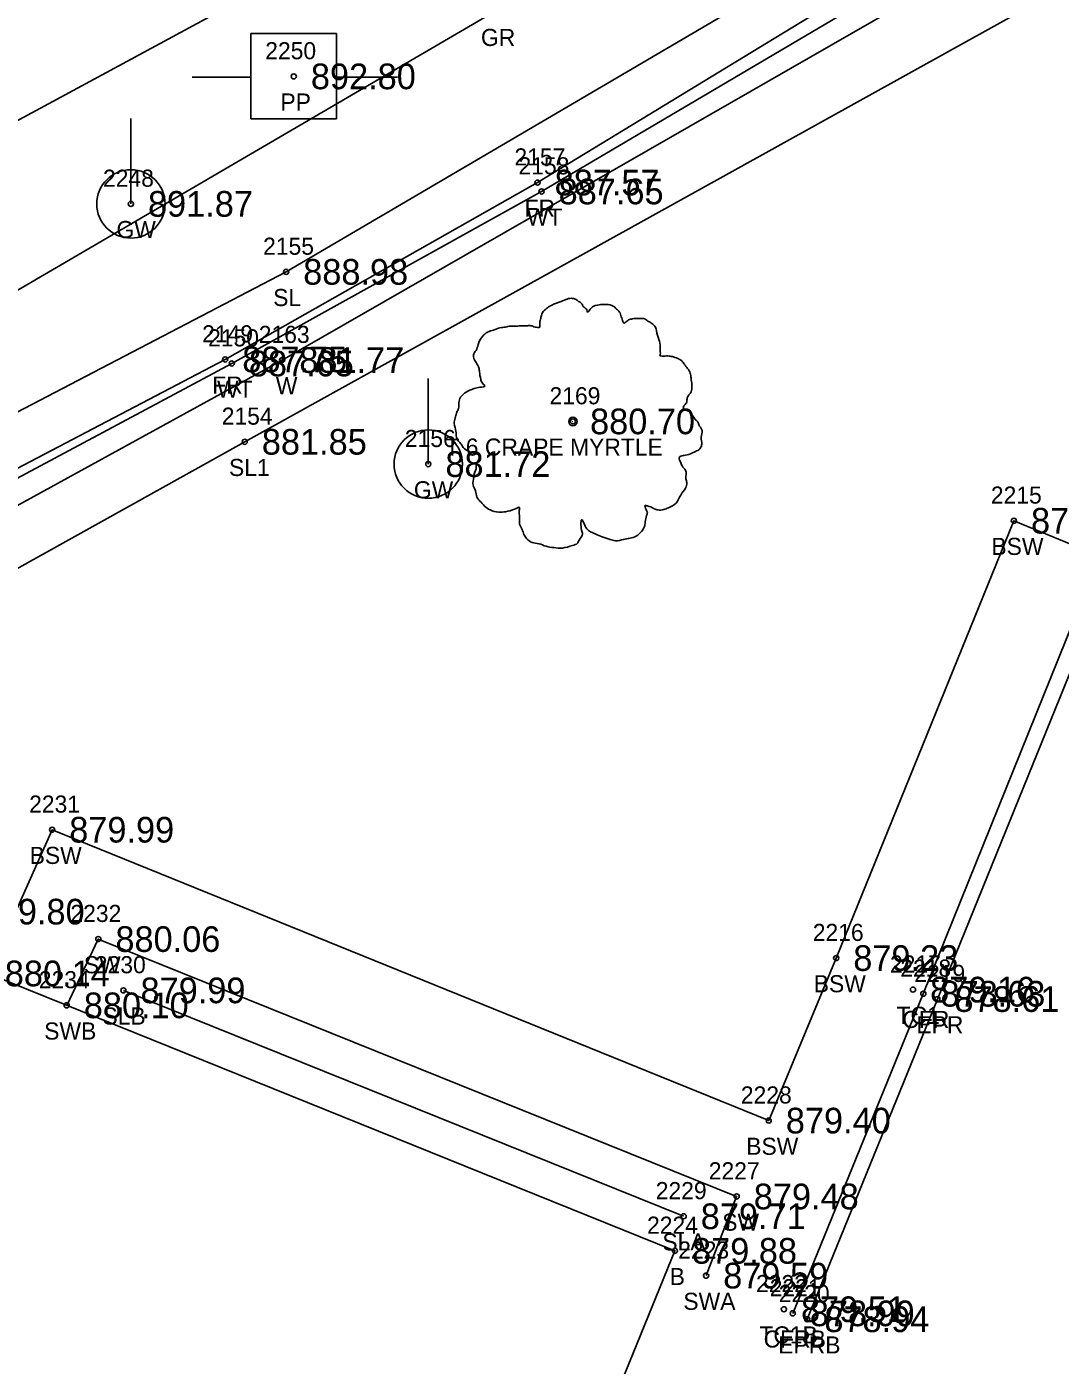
# Model space of a CAD drawing. Extents: x 1622501 to 1626664, y 1117816 to 1121579.
# Drawn here: x 1623395.8 to 1623456.2, y 1118647.2 to 1118725.4 of the extents above; entities that cross this region are included whole.
import ezdxf

# ---------------------------------------------------------------- set-up
doc = ezdxf.new("R2010")
doc.units = 0
for name, color, linetype in [('RD_EX_Bldg', 7, 'Continuous'), ('RD_EX_Bldg_txCode', 7, 'Continuous'), ('RD_EX_BldgApp', 7, 'Continuous'), ('RD_EX_Conc', 7, 'Continuous'), ('RD_EX_Conc_txCode', 7, 'Continuous'), ('RD_EX_Fence_Other', 7, 'Continuous'), ('RD_EX_Fence_Other_txCode', 7, 'Continuous'), ('RD_EX_GuardRail', 7, 'Continuous'), ('RD_EX_GuardRail_txCode', 7, 'Continuous'), ('RD_EX_Misc', 7, 'Continuous'), ('RD_EX_Misc_txCode', 7, 'Continuous'), ('RD_EX_Road', 7, 'Continuous'), ('RD_EX_Road_txCode', 7, 'Continuous'), ('RD_EX_TX_Bldg_ELEV', 7, 'Continuous'), ('RD_EX_TX_Conc_ELEV', 7, 'Continuous'), ('RD_EX_TX_Fence_Other_ELEV', 7, 'Continuous'), ('RD_EX_TX_Misc_ELEV', 7, 'Continuous'), ('RD_EX_TX_Road_ELEV', 7, 'Continuous'), ('RD_EX_TX_UT_ELEV', 7, 'Continuous'), ('RD_EX_TX_VEG_ELEV', 7, 'Continuous'), ('RD_EX_UT', 7, 'Continuous'), ('RD_EX_UT_txCode', 7, 'Continuous'), ('RD_EX_VEG', 7, 'Continuous'), ('RD_EX_VEG_txCode', 7, 'Continuous'), ('RD_HC_Survey_ELEV', 7, 'Continuous'), ('RD_SMD_Locator', 7, 'Continuous')]:
    doc.layers.add(name, color=color, linetype=linetype)

msp = doc.modelspace()

# ---------------------------------------------------------------- linework, layer by layer
at = {"layer": 'RD_EX_Bldg'}
msp.add_lwpolyline([(1623351.424, 1118597.995), (1623382.58, 1118674.507), (1623433.654, 1118653.895), (1623402.498, 1118577.383), (1623351.424, 1118597.995)], dxfattribs=at)
at = {"layer": 'RD_EX_BldgApp'}
msp.add_lwpolyline([(1623362.832, 1118662.827), (1623370.193, 1118681.931), (1623373.866, 1118685.757), (1623410.694, 1118705.967), (1623459.429, 1118733.933), (1623484.083, 1118750.076), (1623515.96, 1118771.434)], dxfattribs=at)
at = {"layer": 'RD_EX_Conc'}
for points in [[(1623287.102, 1118659.692), (1623329.453, 1118683.877), (1623372.881, 1118707.9), (1623416.572, 1118731.516), (1623459.835, 1118756.855), (1623502.097, 1118784.616), (1623542.536, 1118813.857), (1623581.966, 1118844.894), (1623613.887, 1118871.887), (1623619.415, 1118875.421), (1623623.688, 1118876.741), (1623623.459, 1118877.275), (1623631.268, 1118878.694), (1623634.056, 1118878.854), (1623639.628, 1118878.454), (1623640.557, 1118883.374)], [(1623531.882, 1118716.271), (1623516.156, 1118720.453), (1623505.692, 1118721.141), (1623486.378, 1118717.233), (1623473.832, 1118710.301), (1623464.844, 1118702.769), (1623477.624, 1118690.682), (1623478.738, 1118687.446), (1623474.882, 1118687.167), (1623458.276, 1118693.978), (1623448.175, 1118668.923), (1623440.54, 1118650.24)], [(1623458.019, 1118694.702), (1623453.469, 1118696.574), (1623443.082, 1118671.009), (1623439.137, 1118661.507), (1623397.246, 1118678.511), (1623393.478, 1118670.109)], [(1623435.477, 1118652.445), (1623437.262, 1118657.073), (1623399.945, 1118672.119), (1623398.097, 1118668.245)]]:
    msp.add_lwpolyline(points, dxfattribs=at)
at = {"layer": 'RD_EX_Fence_Other'}
msp.add_lwpolyline([(1623360.82, 1118663.932), (1623367.011, 1118680.639), (1623370.331, 1118685.573), (1623375.249, 1118689.174), (1623407.361, 1118706.001), (1623425.619, 1118716.341), (1623480.358, 1118749.66), (1623515.549, 1118772.603)], dxfattribs=at)
at = {"layer": 'RD_EX_GuardRail'}
msp.add_lwpolyline([(1623328.796, 1118667.195), (1623333.583, 1118673.211), (1623349.309, 1118682.841), (1623377.56, 1118699.748), (1623423.094, 1118726.327), (1623463.83, 1118751.666), (1623511.133, 1118780.414)], dxfattribs=at)
at = {"layer": 'RD_EX_Misc'}
msp.add_lwpolyline([(1623362.047, 1118663.092), (1623363.077, 1118666.011), (1623364.471, 1118669.561), (1623365.33, 1118671.673), (1623366.043, 1118673.822), (1623367.273, 1118677.387), (1623367.858, 1118679.553), (1623368.979, 1118682.037), (1623371.277, 1118685.581), (1623375.298, 1118688.415), (1623407.747, 1118705.764), (1623425.855, 1118715.821), (1623458.998, 1118735.378), (1623483.907, 1118751.097), (1623484.139, 1118751.024), (1623515.704, 1118772.555)], dxfattribs=at)
at = {"layer": 'RD_EX_Road'}
msp.add_lwpolyline([(1623529.611, 1118716.171), (1623516.152, 1118719.483), (1623505.742, 1118720.286), (1623486.757, 1118716.386), (1623474.282, 1118709.658), (1623466.206, 1118702.886), (1623478.169, 1118691.689), (1623479.562, 1118687.18), (1623474.442, 1118686.423), (1623458.812, 1118692.747), (1623448.994, 1118668.612), (1623441.391, 1118649.895)], dxfattribs=at)
at = {"layer": 'RD_EX_UT'}
for p, q in [((1623413.863, 1118725.058), (1623408.863, 1118725.058)), ((1623408.863, 1118725.058), (1623408.863, 1118720.058)), ((1623413.863, 1118720.058), (1623413.863, 1118725.058)), ((1623405.432, 1118722.495), (1623408.901, 1118722.495)), ((1623413.791, 1118722.495), (1623417.432, 1118722.495)), ((1623401.849, 1118715.096), (1623401.849, 1118720.096)), ((1623408.863, 1118720.058), (1623413.863, 1118720.058)), ((1623419.236, 1118699.883), (1623419.236, 1118704.883))]:
    msp.add_line(p, q, dxfattribs=at)
for centre in [(1623401.849, 1118715.096), (1623419.236, 1118699.883)]:
    msp.add_circle(centre, 1.999, dxfattribs=at)
at = {"layer": 'RD_EX_VEG'}
msp.add_line((1623434.163, 1118655.915), (1623401.413, 1118669.12), dxfattribs=at)
for points in [[(1623371.315, 1118690.471), (1623410.924, 1118711.122), (1623478.591, 1118750.831), (1623514.185, 1118775.518)], [(1623357.099, 1118658.576), (1623354.417, 1118653.307), (1623360.309, 1118652.881), (1623372.824, 1118681.33), (1623408.505, 1118701.188), (1623470.644, 1118735.679), (1623505.961, 1118762.905)]]:
    msp.add_lwpolyline(points, dxfattribs=at)
for centre, radius in [((1623427.692, 1118702.38), 0.25), ((1623427.679, 1118702.361), 0.0001)]:
    msp.add_circle(centre, radius, dxfattribs=at)
for points in [[(1623427.824, 1118709.547), (1623427.524, 1118709.572), (1623427.199, 1118709.472), (1623426.949, 1118709.372), (1623426.724, 1118709.297), (1623426.499, 1118709.197), (1623426.199, 1118709.022), (1623425.975, 1118708.822), (1623425.85, 1118708.573), (1623425.8, 1118708.348), (1623425.75, 1118708.073), (1623425.75, 1118707.898), (1623425.625, 1118707.873), (1623425.475, 1118707.898), (1623425.225, 1118707.973), (1623424.975, 1118707.973), (1623424.725, 1118707.973), (1623424.375, 1118707.948), (1623424.025, 1118707.948), (1623423.751, 1118707.898), (1623423.426, 1118707.848), (1623423.051, 1118707.723), (1623422.701, 1118707.598), (1623422.401, 1118707.348), (1623422.151, 1118706.873), (1623422.026, 1118706.523), (1623421.876, 1118706.274), (1623422.026, 1118705.824), (1623422.201, 1118705.474), (1623422.226, 1118705.274), (1623422.301, 1118704.849), (1623422.401, 1118704.624), (1623422.526, 1118704.424), (1623422.451, 1118704.399), (1623422.076, 1118704.349), (1623421.776, 1118704.249), (1623421.352, 1118704.025), (1623421.127, 1118703.8), (1623421.027, 1118703.475), (1623421.002, 1118703.125), (1623420.902, 1118702.925), (1623420.827, 1118702.65), (1623420.802, 1118702.575), (1623420.752, 1118702.25), (1623420.852, 1118701.8), (1623420.877, 1118701.451), (1623421.002, 1118701.226), (1623421.152, 1118701.051), (1623421.327, 1118700.801), (1623421.726, 1118700.576), (1623422.051, 1118700.476), (1623422.251, 1118700.451), (1623422.076, 1118699.951), (1623422.026, 1118699.601), (1623421.901, 1118699.202), (1623421.901, 1118699.127), (1623421.851, 1118698.652), (1623422.001, 1118698.327), (1623422.076, 1118697.952), (1623422.251, 1118697.727), (1623422.526, 1118697.427), (1623422.851, 1118697.203), (1623423.351, 1118697.078), (1623423.751, 1118697.103), (1623424.325, 1118697.277), (1623424.575, 1118697.352), (1623424.55, 1118697.178), (1623424.575, 1118696.803), (1623424.575, 1118696.378), (1623424.725, 1118696.053), (1623424.825, 1118695.778), (1623424.975, 1118695.528), (1623425.3, 1118695.303), (1623425.7, 1118695.228), (1623426.124, 1118695.078), (1623426.574, 1118695.003), (1623427.074, 1118694.978), (1623427.674, 1118695.128), (1623427.949, 1118695.253), (1623428.049, 1118695.428), (1623428.249, 1118695.803), (1623428.199, 1118696.028), (1623428.224, 1118696.628), (1623428.323, 1118696.453), (1623428.498, 1118696.103), (1623428.998, 1118695.803), (1623429.398, 1118695.628), (1623429.873, 1118695.478), (1623430.173, 1118695.403), (1623430.647, 1118695.478), (1623431.022, 1118695.553), (1623431.397, 1118695.678), (1623431.697, 1118695.953), (1623431.872, 1118696.228), (1623431.922, 1118696.503), (1623431.997, 1118696.878), (1623432.047, 1118697.053)], [(1623432.047, 1118697.053), (1623431.972, 1118697.228), (1623431.922, 1118697.477), (1623431.997, 1118697.452), (1623432.172, 1118697.402), (1623432.447, 1118697.277), (1623432.672, 1118697.203), (1623432.996, 1118697.228), (1623433.271, 1118697.327), (1623433.721, 1118697.602), (1623433.996, 1118698.077), (1623434.271, 1118698.477), (1623434.346, 1118698.802), (1623434.296, 1118699.027), (1623434.271, 1118699.526), (1623434.071, 1118699.776), (1623434.021, 1118699.901), (1623433.921, 1118700.301), (1623433.996, 1118700.351), (1623434.271, 1118700.401), (1623434.646, 1118700.526), (1623434.921, 1118700.651), (1623435.146, 1118700.826), (1623435.22, 1118701.051), (1623435.196, 1118701.451), (1623435.245, 1118701.85), (1623435.171, 1118702), (1623435.071, 1118702.15), (1623434.996, 1118702.35), (1623434.846, 1118702.5), (1623434.746, 1118702.65), (1623434.646, 1118702.75), (1623434.521, 1118702.9), (1623434.346, 1118703.025), (1623434.196, 1118703.075), (1623434.146, 1118703.225), (1623434.296, 1118703.425), (1623434.346, 1118703.525), (1623434.371, 1118703.75), (1623434.596, 1118704.099), (1623434.646, 1118704.499), (1623434.596, 1118704.924), (1623434.546, 1118705.199), (1623434.396, 1118705.474), (1623434.196, 1118705.724), (1623434.071, 1118705.899), (1623433.896, 1118706.024), (1623433.571, 1118706.149), (1623433.321, 1118706.199), (1623432.971, 1118706.199), (1623432.772, 1118706.249), (1623432.797, 1118706.299), (1623432.797, 1118706.448), (1623432.797, 1118706.723), (1623432.722, 1118707.173), (1623432.572, 1118707.673), (1623432.572, 1118707.698), (1623432.472, 1118707.948), (1623432.247, 1118708.148), (1623432.072, 1118708.248), (1623431.872, 1118708.373), (1623431.622, 1118708.398), (1623431.322, 1118708.398), (1623431.047, 1118708.348), (1623430.847, 1118708.248), (1623430.672, 1118708.123), (1623430.597, 1118708.273), (1623430.498, 1118708.573), (1623430.448, 1118708.722), (1623430.298, 1118708.897), (1623430.073, 1118709.097), (1623429.623, 1118709.222), (1623428.998, 1118709.147), (1623428.698, 1118708.947), (1623428.548, 1118708.772), (1623428.498, 1118708.897), (1623428.298, 1118709.097), (1623428.199, 1118709.272), (1623428.024, 1118709.397), (1623427.874, 1118709.497), (1623427.774, 1118709.547)]]:
    msp.add_spline(points, degree=3, dxfattribs=at)
at = {"layer": 'RD_SMD_Locator'}
for centre in [(1623411.372, 1118722.549), (1623425.619, 1118716.341), (1623425.855, 1118715.821), (1623401.849, 1118715.096), (1623410.924, 1118711.122), (1623407.361, 1118706.001), (1623410.694, 1118705.967), (1623407.747, 1118705.764), (1623427.692, 1118702.38), (1623408.505, 1118701.188), (1623419.236, 1118699.883), (1623453.469, 1118696.574), (1623397.246, 1118678.511), (1623399.945, 1118672.119), (1623443.082, 1118671.009), (1623401.413, 1118669.12), (1623447.571, 1118669.164), (1623448.175, 1118668.923), (1623448.994, 1118668.612), (1623398.097, 1118668.245), (1623439.137, 1118661.507), (1623437.262, 1118657.073), (1623434.163, 1118655.915), (1623433.654, 1118653.895), (1623435.477, 1118652.445), (1623440.023, 1118650.48), (1623440.54, 1118650.24), (1623441.391, 1118649.895)]:
    msp.add_circle(centre, 0.15, dxfattribs=at)

# ---------------------------------------------------------------- texts
at = {"layer": 'RD_EX_Bldg_txCode'}
for s, p in [('2224', (1623432.024, 1118654.895)), ('B', (1623433.347, 1118651.895))]:
    msp.add_text(s, height=1, dxfattribs=at).set_placement(p)
at = {"layer": 'RD_EX_Conc_txCode'}
for s, p in [('2215', (1623452.123, 1118697.574)), ('BSW', (1623452.154, 1118694.574)), ('2231', (1623395.9, 1118679.511)), ('BSW', (1623395.931, 1118676.511)), ('2232', (1623398.315, 1118673.119)), ('2216', (1623441.712, 1118672.009)), ('SW', (1623399.103, 1118670.119)), ('2217', (1623446.225, 1118670.164)), ('2218', (1623446.828, 1118669.923)), ('2234', (1623396.467, 1118669.245)), ('BSW', (1623441.767, 1118669.009)), ('TC1', (1623446.61, 1118667.164)), ('CFR', (1623446.947, 1118666.923)), ('SWB', (1623396.782, 1118666.245)), ('2228', (1623437.507, 1118662.507)), ('BSW', (1623437.822, 1118659.507)), ('2227', (1623435.632, 1118658.073)), ('SW', (1623436.419, 1118655.073)), ('2223', (1623433.847, 1118653.445)), ('2222', (1623438.393, 1118651.48)), ('2221', (1623439.194, 1118651.24)), ('SWA', (1623434.146, 1118650.445)), ('TC1B', (1623438.59, 1118648.48)), ('CFRB', (1623438.839, 1118648.24))]:
    msp.add_text(s, height=1, dxfattribs=at).set_placement(p)
at = {"layer": 'RD_EX_Fence_Other_txCode'}
for s, p in [('2157', (1623424.273, 1118717.341)), ('FR', (1623424.863, 1118714.341)), ('2149', (1623406.015, 1118707.001)), ('FR', (1623406.605, 1118704.001))]:
    msp.add_text(s, height=1, dxfattribs=at).set_placement(p)
at = {"layer": 'RD_EX_GuardRail_txCode'}
msp.add_text('GR', height=1, dxfattribs=at).set_placement((1623422.314, 1118724.327))
at = {"layer": 'RD_EX_Misc_txCode'}
for s, p in [('2158', (1623424.509, 1118716.821)), ('WT', (1623424.997, 1118713.821)), ('2150', (1623406.361, 1118706.764)), ('2163', (1623409.324, 1118706.967)), ('WT', (1623406.889, 1118703.764)), ('W', (1623410.324, 1118703.967))]:
    msp.add_text(s, height=1, dxfattribs=at).set_placement(p)
at = {"layer": 'RD_EX_Road_txCode'}
for s, p in [('2219', (1623447.648, 1118669.612)), ('EPR', (1623447.766, 1118666.612)), ('2220', (1623439.722, 1118650.895)), ('EPRB', (1623439.691, 1118647.895))]:
    msp.add_text(s, height=1, dxfattribs=at).set_placement(p)
at = {"layer": 'RD_EX_TX_Bldg_ELEV'}
msp.add_text('879.88', height=1.5, dxfattribs=at).set_placement((1623434.654, 1118653.145))
at = {"layer": 'RD_EX_TX_Conc_ELEV'}
for s, p in [('878.63', (1623454.469, 1118695.824)), ('879.99', (1623398.246, 1118677.761)), ('880.06', (1623400.945, 1118671.369)), ('879.23', (1623444.082, 1118670.259)), ('880.14', (1623394.478, 1118669.359)), ('879.16', (1623448.571, 1118668.414)), ('878.63', (1623449.175, 1118668.173)), ('880.10', (1623399.097, 1118667.495)), ('879.40', (1623440.137, 1118660.757)), ('879.48', (1623438.262, 1118656.323)), ('879.59', (1623436.477, 1118651.695)), ('879.51', (1623441.023, 1118649.73)), ('878.99', (1623441.54, 1118649.49))]:
    msp.add_text(s, height=1.5, dxfattribs=at).set_placement(p)
at = {"layer": 'RD_EX_TX_Fence_Other_ELEV'}
for s, p in [('887.57', (1623426.619, 1118715.591)), ('887.75', (1623408.361, 1118705.251))]:
    msp.add_text(s, height=1.5, dxfattribs=at).set_placement(p)
at = {"layer": 'RD_EX_TX_Misc_ELEV'}
for s, p in [('887.65', (1623426.855, 1118715.071)), ('887.65', (1623408.747, 1118705.014)), ('881.77', (1623411.694, 1118705.217)), ('879.80', (1623393.012, 1118672.973))]:
    msp.add_text(s, height=1.5, dxfattribs=at).set_placement(p)
at = {"layer": 'RD_EX_TX_Road_ELEV'}
for s, p in [('878.61', (1623449.994, 1118667.862)), ('878.94', (1623442.391, 1118649.145))]:
    msp.add_text(s, height=1.5, dxfattribs=at).set_placement(p)
at = {"layer": 'RD_EX_TX_UT_ELEV'}
for s, p in [('891.87', (1623402.849, 1118714.346)), ('881.72', (1623420.236, 1118699.133))]:
    msp.add_text(s, height=1.5, dxfattribs=at).set_placement(p)
at = {"layer": 'RD_EX_TX_VEG_ELEV'}
for s, p in [('888.98', (1623411.924, 1118710.372)), ('880.70', (1623428.692, 1118701.63)), ('881.85', (1623409.505, 1118700.438)), ('879.99', (1623402.413, 1118668.37)), ('879.71', (1623435.163, 1118655.165))]:
    msp.add_text(s, height=1.5, dxfattribs=at).set_placement(p)
at = {"layer": 'RD_EX_UT_txCode'}
for s, p in [('2250', (1623409.703, 1118723.549)), ('PP', (1623410.592, 1118720.549)), ('2248', (1623400.219, 1118716.096)), ('GW', (1623401.006, 1118713.096)), ('2156', (1623417.866, 1118700.883)), ('GW', (1623418.393, 1118697.883))]:
    msp.add_text(s, height=1, dxfattribs=at).set_placement(p)
at = {"layer": 'RD_EX_VEG_txCode'}
for s, p in [('2155', (1623409.578, 1118712.122)), ('SL', (1623410.168, 1118709.122)), ('2169', (1623426.322, 1118703.38)), ('2154', (1623407.159, 1118702.188)), ('T 6 CRAPE MYRTLE', (1623420.239, 1118700.38)), ('SL1', (1623407.584, 1118699.188)), ('2230', (1623399.744, 1118670.12)), ('SLB', (1623400.185, 1118667.12)), ('2229', (1623432.533, 1118656.915)), ('SLA', (1623432.919, 1118653.915))]:
    msp.add_text(s, height=1, dxfattribs=at).set_placement(p)
at = {"layer": 'RD_HC_Survey_ELEV'}
msp.add_text('892.80', height=1.5, dxfattribs=at).set_placement((1623412.372, 1118721.799))

doc.saveas('drawing.dxf')
